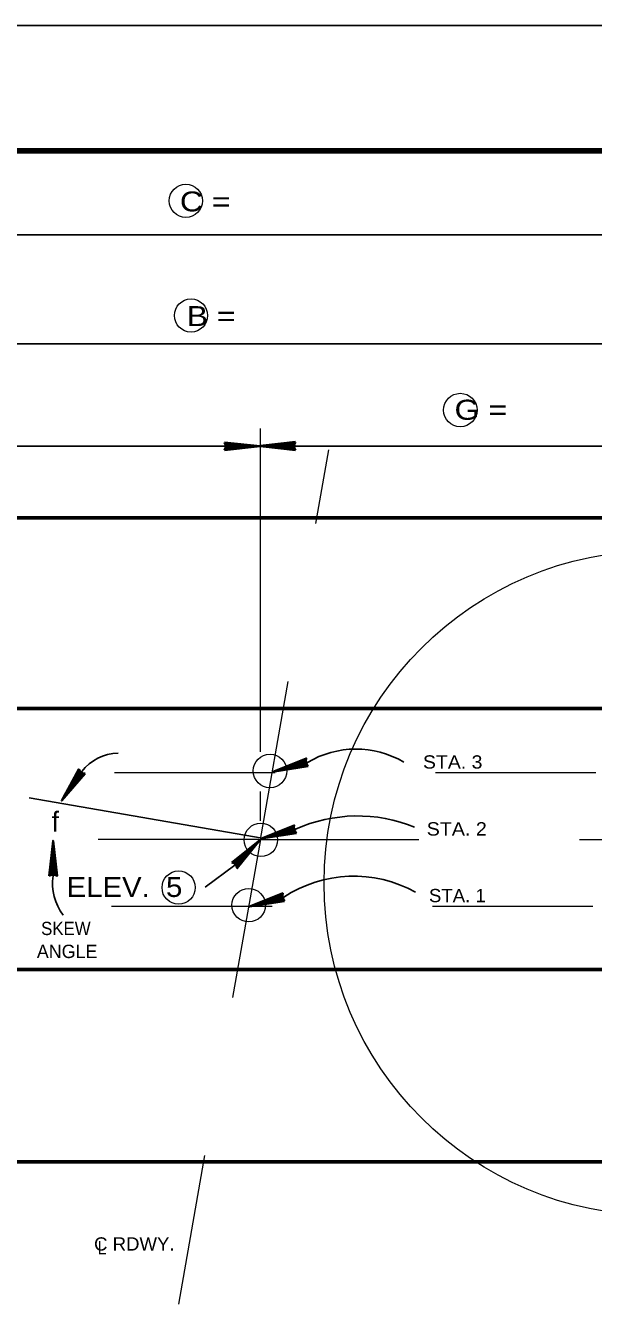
# Model space of a CAD drawing. Extents: x 1.6 to 19.9, y 2.8 to 9.5.
# Drawn here: x 16.884 to 17.238, y 8.746 to 9.545 of the extents above; entities that cross this region are included whole.
import ezdxf

# ---------------------------------------------------------------- set-up
doc = ezdxf.new("R2010")
doc.units = 0
doc.header["$LTSCALE"] = 0.0047
doc.linetypes.add('DOT_DASHED', pattern=[7.7, 5, -1.2, 0.3, -1.2])
doc.layers.add('1', color=7, linetype='Continuous', lineweight=35)
doc.layers.add('5', color=7, linetype='Continuous', lineweight=13)

msp = doc.modelspace()

# ---------------------------------------------------------------- linework, layer by layer
at = {"layer": '1', "lineweight": 25}
for p, q in [((19.894917, 9.545083), (16.26675, 9.545083)), ((16.629583, 9.414833), (17.4315, 9.414833)), ((16.633583, 9.34675), (17.42725, 9.34675)), ((16.730833, 9.283083), (17.332167, 9.283083))]:
    msp.add_line(p, q, dxfattribs=at)
at = {"layer": '1', "lineweight": 13}
for p, q in [((17.0305, 9.294167), (17.0305, 9.092583)), ((17.0305, 9.067917), (17.0305, 9.0495))]:
    msp.add_line(p, q, dxfattribs=at)
at = {"layer": '1'}
for p, q in [((17.00825, 9.285417), (17.0305, 9.283)), ((17.00825, 9.283), (17.0305, 9.283)), ((17.030583, 9.283), (17.008333, 9.2805)), ((17.008583, 9.281583), (17.024083, 9.28325)), ((17.008667, 9.285083), (17.02525, 9.28325)), ((17.008667, 9.285), (17.02525, 9.283167)), ((17.008667, 9.284917), (17.02525, 9.283083)), ((17.008667, 9.284667), (17.02525, 9.282833)), ((17.008667, 9.281333), (17.024083, 9.283)), ((17.008667, 9.281083), (17.024167, 9.28275)), ((17.00875, 9.285167), (17.02525, 9.283333)), ((17.00875, 9.280833), (17.024167, 9.282583)), ((17.0305, 9.283167), (17.052583, 9.285667)), ((17.052583, 9.283083), (17.0305, 9.283083)), ((17.052583, 9.280667), (17.0305, 9.283083)), ((17.052083, 9.281), (17.035667, 9.282833)), ((17.052083, 9.281083), (17.035667, 9.282833)), ((17.052083, 9.280917), (17.035667, 9.28275)), ((17.052167, 9.281417), (17.03575, 9.283167)), ((17.052083, 9.281167), (17.03575, 9.283)), ((17.052083, 9.285167), (17.03675, 9.2835)), ((17.052083, 9.285), (17.03675, 9.283333)), ((17.052167, 9.28475), (17.036833, 9.283083)), ((17.052167, 9.2845), (17.036833, 9.282833)), ((17.059, 9.088), (17.044667, 9.082333)), ((17.059167, 9.087833), (17.044667, 9.08225)), ((16.9195, 9.080417), (16.906833, 9.06225)), ((16.917417, 9.081083), (16.910083, 9.067583)), ((16.917667, 9.081083), (16.910167, 9.067583)), ((16.917833, 9.080917), (16.910417, 9.067333)), ((16.918167, 9.080833), (16.910667, 9.067333)), ((17.06, 9.085917), (17.0385, 9.080167)), ((17.059917, 9.084333), (17.043667, 9.081833)), ((17.06, 9.084083), (17.043667, 9.0815)), ((17.06, 9.083917), (17.043667, 9.08125)), ((17.06, 9.084), (17.04375, 9.081333)), ((17.06, 9.083833), (17.04375, 9.08125)), ((17.059083, 9.087583), (17.044833, 9.081917)), ((17.05925, 9.087333), (17.044833, 9.0815)), ((16.9205, 9.079083), (16.909667, 9.066583)), ((16.92075, 9.079), (16.909833, 9.066417)), ((16.920917, 9.078917), (16.909917, 9.066333)), ((16.92075, 9.078917), (16.909917, 9.066417)), ((16.920917, 9.07875), (16.910083, 9.066333)), ((17.05275, 9.044417), (17.031333, 9.0385)), ((17.052667, 9.042583), (17.03625, 9.04025)), ((17.05275, 9.042333), (17.03625, 9.040083)), ((17.052833, 9.04225), (17.03625, 9.039833)), ((17.05275, 9.042333), (17.036333, 9.039833)), ((17.05275, 9.042083), (17.036333, 9.039833)), ((17.051583, 9.046333), (17.03725, 9.04075)), ((17.05175, 9.046083), (17.03725, 9.040583)), ((17.051667, 9.045833), (17.037417, 9.040333)), ((17.05175, 9.045667), (17.037417, 9.040083)), ((16.89925, 9.01575), (16.901167, 9.032083)), ((16.899417, 9.01575), (16.90125, 9.032083)), ((16.8995, 9.01575), (16.90125, 9.032083)), ((16.8995, 9.01575), (16.901417, 9.032083)), ((16.899833, 9.015583), (16.901583, 9.032083)), ((16.9015, 9.01525), (16.9015, 9.037167)), ((17.013417, 9.023833), (17.026333, 9.034083)), ((17.013417, 9.02375), (17.026417, 9.034083)), ((17.013417, 9.023583), (17.0265, 9.034)), ((17.013583, 9.023583), (17.0265, 9.033917)), ((17.013667, 9.023417), (17.026667, 9.033667)), ((17.014667, 9.021917), (17.03025, 9.0375)), ((17.015833, 9.021167), (17.025583, 9.033167)), ((17.016, 9.021083), (17.025667, 9.033083)), ((17.01625, 9.020917), (17.025917, 9.032833)), ((17.016333, 9.02075), (17.026, 9.032833)), ((16.902917, 9.015583), (16.90125, 9.031)), ((16.903167, 9.015583), (16.9015, 9.031)), ((16.903417, 9.01575), (16.901833, 9.031083)), ((16.9035, 9.01575), (16.902, 9.031083)), ((17.04525, 9.002), (17.023917, 8.99625)), ((17.04525, 9.000333), (17.028833, 8.997833)), ((17.04525, 9.000083), (17.028833, 8.997583)), ((17.045417, 9), (17.028833, 8.997333)), ((17.04525, 9), (17.028917, 8.997417)), ((17.044333, 9.003917), (17.029833, 8.998333)), ((17.0445, 9.003833), (17.029833, 8.998167)), ((17.0445, 9.0035), (17.03, 8.997917)), ((17.044583, 9.003333), (17.03, 8.997583)), ((17.04525, 8.999667), (17.028917, 8.997333))]:
    msp.add_line(p, q, dxfattribs=at)
at = {"layer": '1', "linetype": 'DOT_DASHED', "lineweight": 13}
for p, q in [((17.030667, 9.037917), (17.073333, 9.28075)), ((16.539833, 9.079667), (17.478917, 9.079667)), ((17.0295, 9.038), (16.532083, 9.038)), ((17.030667, 9.037917), (16.979583, 8.7485)), ((17.0295, 9.038), (17.478917, 9.038)), ((16.537917, 8.996417), (17.4745, 8.996417))]:
    msp.add_line(p, q, dxfattribs=at)
at = {"layer": '1', "lineweight": 60}
for p, q in [((16.731, 9.119583), (17.252, 9.119583)), ((16.731, 8.957), (17.25775, 8.957)), ((17.43225, 8.837167), (16.629667, 8.837167))]:
    msp.add_line(p, q, dxfattribs=at)
at = {"layer": '1', "lineweight": 106}
msp.add_lwpolyline([(19.823, 7.367), (19.823, 9.467), (16.423, 9.467), (16.423, 7.367)], dxfattribs=at)
at = {"layer": '1'}
for points in [[(17.00825, 9.2805), (17.009417, 9.283), (17.00825, 9.285417)], [(17.00975, 9.28325), (17.019667, 9.283417), (17.019583, 9.283167), (17.01775, 9.28325), (17.00975, 9.283417), (17.016167, 9.283583), (17.0095, 9.28375), (17.014083, 9.283917), (17.00925, 9.284167), (17.016917, 9.283583), (17.02675, 9.283167), (17.02475, 9.282583), (17.0275, 9.282833), (17.00975, 9.28275), (17.014917, 9.282417), (17.0095, 9.282417), (17.02075, 9.283167), (17.009333, 9.282), (17.009833, 9.283167), (17.008833, 9.28475), (17.009333, 9.284417), (17.009833, 9.283583), (17.010333, 9.283833), (17.009917, 9.2845), (17.009583, 9.282917), (17.009167, 9.282), (17.00875, 9.280917)], [(17.051083, 9.282833), (17.04125, 9.282667), (17.04125, 9.282917), (17.043167, 9.282833), (17.051083, 9.282667), (17.04475, 9.2825), (17.051333, 9.282333), (17.046667, 9.282167), (17.0515, 9.281917), (17.044, 9.2825), (17.034167, 9.282917), (17.036167, 9.2835), (17.0335, 9.28325), (17.051083, 9.283333), (17.045917, 9.283667), (17.051333, 9.283667), (17.040083, 9.282833), (17.051417, 9.284083), (17.051, 9.282833), (17.051917, 9.281333), (17.051417, 9.281667), (17.051, 9.2825), (17.050417, 9.28225), (17.050833, 9.281583), (17.051167, 9.283167), (17.051583, 9.284083), (17.052083, 9.285167)], [(17.052583, 9.285583), (17.051417, 9.283083), (17.052583, 9.280667)], [(17.058667, 9.085333), (17.049167, 9.082667), (17.04925, 9.083), (17.051, 9.083333), (17.058667, 9.085167), (17.052583, 9.0835), (17.059, 9.084917), (17.054667, 9.083583), (17.059333, 9.084583), (17.051667, 9.08325), (17.042167, 9.080917), (17.043917, 9.08225), (17.0415, 9.081083), (17.0585, 9.085667), (17.0535, 9.084833), (17.058667, 9.086167), (17.048083, 9.082667), (17.058667, 9.086667), (17.0585, 9.085333), (17.05975, 9.084167), (17.05925, 9.084333), (17.058667, 9.084917), (17.05825, 9.084583), (17.05875, 9.084167), (17.05875, 9.085667), (17.05875, 9.08675), (17.059, 9.087917)], [(16.91875, 9.079083), (16.913167, 9.070833), (16.913083, 9.071), (16.914167, 9.072417), (16.918917, 9.079), (16.9155, 9.073583), (16.919417, 9.078917), (16.916833, 9.075167), (16.919833, 9.078917), (16.915, 9.072833), (16.909083, 9.065333), (16.90975, 9.067167), (16.908333, 9.065), (16.918417, 9.079333), (16.91525, 9.075333), (16.91825, 9.079667), (16.9125, 9.070083), (16.918083, 9.08), (16.918667, 9.079), (16.9205, 9.078917), (16.92, 9.07875), (16.919, 9.078833), (16.918917, 9.078333), (16.91975, 9.078333), (16.918667, 9.079333), (16.918167, 9.080167), (16.917417, 9.081083)], [(17.051167, 9.043833), (17.04175, 9.041), (17.04175, 9.041333), (17.043667, 9.041667), (17.051167, 9.04375), (17.045167, 9.04175), (17.0515, 9.0435), (17.047167, 9.041917), (17.052, 9.042917), (17.0445, 9.0415), (17.034833, 9.0395), (17.036583, 9.040583), (17.034, 9.039583), (17.051, 9.044167), (17.046, 9.043333), (17.051167, 9.044583), (17.040667, 9.041), (17.051167, 9.045083), (17.051083, 9.043833), (17.052583, 9.042417), (17.05175, 9.042583), (17.051167, 9.0435), (17.05075, 9.042917), (17.05125, 9.042417), (17.051333, 9.044167), (17.051333, 9.045083), (17.0515, 9.04625)], [(16.90125, 9.01675), (16.901167, 9.026583), (16.901333, 9.026583), (16.90125, 9.024583), (16.901167, 9.01675), (16.900917, 9.023083), (16.900833, 9.0165), (16.900583, 9.021167), (16.900333, 9.016333), (16.900917, 9.023833), (16.901333, 9.0335), (16.902, 9.031583), (16.90175, 9.034167), (16.901833, 9.01675), (16.902167, 9.021917), (16.902167, 9.0165), (16.90125, 9.02775), (16.9025, 9.016417), (16.90125, 9.016833), (16.899833, 9.015833), (16.900083, 9.016417), (16.900917, 9.016833), (16.900583, 9.0175), (16.9, 9.016917), (16.901583, 9.016667), (16.9025, 9.01625), (16.9035, 9.01575)], [(17.015417, 9.023167), (17.022333, 9.03025), (17.0225, 9.030083), (17.021083, 9.02875), (17.015333, 9.023333), (17.01975, 9.027917), (17.015, 9.023333), (17.018083, 9.026833), (17.0145, 9.0235), (17.02025, 9.028417), (17.0275, 9.035167), (17.0265, 9.033167), (17.02825, 9.035417), (17.015833, 9.022833), (17.019667, 9.026333), (17.015833, 9.0225), (17.02325, 9.030917), (17.016, 9.022083), (17.015583, 9.023167), (17.01375, 9.023583), (17.014417, 9.02375), (17.01525, 9.0235), (17.015417, 9.023917), (17.01475, 9.024083), (17.015583, 9.022833), (17.015917, 9.021917), (17.016333, 9.020833)], [(17.043917, 9.001417), (17.034333, 8.998667), (17.034417, 8.998917), (17.03625, 8.999333), (17.043917, 9.001333), (17.03775, 8.999417), (17.04425, 9.001083), (17.04, 8.999583), (17.044667, 9.000583), (17.037, 8.999167), (17.0275, 8.997083), (17.029167, 8.998167), (17.026667, 8.99725), (17.04375, 9.00175), (17.0385, 9.000917), (17.043917, 9.002167), (17.03325, 8.998667), (17.043917, 9.002583), (17.043833, 9.001417), (17.045167, 9.00025), (17.044583, 9.000333), (17.043917, 9.001083), (17.043417, 9.000583), (17.043917, 9.00025), (17.044167, 9.00175), (17.044167, 9.002667), (17.04425, 9.003917)]]:
    msp.add_lwpolyline(points, dxfattribs=at)
at = {"layer": '1', "lineweight": 60}
msp.add_lwpolyline([(16.629667, 8.837167), (16.629667, 9.2385), (17.43225, 9.2385)], dxfattribs=at)
at = {"layer": '1'}
for points in [[(17.060417, 9.083583), (17.0385, 9.080167), (17.05925, 9.0885), (17.058833, 9.085667)], [(16.921417, 9.079083), (16.906833, 9.06225), (16.917417, 9.08175), (16.918833, 9.0795)], [(17.05325, 9.041917), (17.031333, 9.0385), (17.05175, 9.04675), (17.051417, 9.044167)], [(16.899083, 9.01525), (16.9015, 9.037167), (16.904, 9.01525), (16.9015, 9.016417)], [(17.012833, 9.023583), (17.03025, 9.0375), (17.01625, 9.020083), (17.015417, 9.022833)], [(17.04575, 8.999583), (17.023917, 8.99625), (17.044583, 9.0045), (17.04425, 9.00175)]]:
    msp.add_lwpolyline(points, close=True, dxfattribs=at)
at = {"layer": '1', "lineweight": 13}
for centre, radius in [((16.984196, 9.435947), 0.010363), ((16.987429, 9.364481), 0.010363), ((17.155292, 9.305562), 0.010417), ((17.277479, 9.010857), 0.207058), ((17.036686, 9.080687), 0.010445), ((17.030965, 9.037741), 0.010445), ((16.979719, 9.008017), 0.010363), ((17.023421, 8.997034), 0.010445)]:
    msp.add_circle(centre, radius, dxfattribs=at)
at = {"layer": '5', "lineweight": 25}
for p, q in [((17.031833, 9.03875), (16.8865, 9.064)), ((17.014667, 9.021917), (16.996167, 9.00825))]:
    msp.add_line(p, q, dxfattribs=at)
for centre, radius, start, end in [((16.942339, 9.062945), 0.028831, 90.76421, 142.70243), ((17.090237, 9.035335), 0.058969, 59.64297, 120.83185), ((17.091285, 8.958356), 0.094282, 67.84713, 114.20121), ((16.932671, 9.010308), 0.031564, 170.99053, 217.99721), ((17.08886, 8.935937), 0.079143, 60.84448, 123.43193)]:
    msp.add_arc(centre, radius, start, end, dxfattribs=at)

# ---------------------------------------------------------------- texts
at = {"layer": '1'}
for s, height, width, p in [('STA. 3', 0.00825, 1.1, (17.132, 9.082167)), ('STA. 2', 0.008333, 1.1, (17.134333, 9.040417)), ('STA. 1', 0.00825, 1.05, (17.13575, 8.998917)), ('SKEW', 0.00825, 0.95, (16.894, 8.978417)), ('C RDWY.', 0.008249, 1.05, (16.927, 8.781833)), ('L', 0.008333, 0.9, (16.929167, 8.779417))]:
    msp.add_text(s, height=height, dxfattribs=dict(at, width=width)).set_placement(p)
for s, height, p in [('f ', 0.01242, (16.900583, 9.042917)), ('ANGLE', 0.008333, (16.891333, 8.964083))]:
    msp.add_text(s, height=height, dxfattribs=at).set_placement(p)
at = {"layer": '5'}
for s, height, width, p in [('C =      ', 0.01242, 1.2, (16.9805, 9.429333)), ('B =      ', 0.01242, 1.2, (16.98475, 9.357917)), ('G =      ', 0.0125, 1.2, (17.151667, 9.2995)), ('ELEV.  5', 0.01242, 1.1, (16.909917, 9.002167))]:
    msp.add_text(s, height=height, dxfattribs=dict(at, width=width)).set_placement(p)

doc.saveas('drawing.dxf')
